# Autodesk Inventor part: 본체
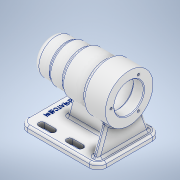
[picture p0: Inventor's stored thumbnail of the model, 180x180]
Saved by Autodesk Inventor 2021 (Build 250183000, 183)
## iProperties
Created: 2022-07
Part Number: 본체
Material: 알루미늄 6061
Document SubType Name: Modeling
Designer: owner
Density: 2.7 g/cm^3
Appearance: 알루미늄 - 평지
Mass: 693.151 g
Surface Area: 698.728 cm^2
Volume: 256.723 cm^3
Author: owner
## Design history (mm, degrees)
sketch "스케치1"
  geometry: L1 (44, 45)-(-44, 45); L2 (-56, 33)-(-56, -33); L3 (-44, -45)-(44, -45); L4 (56, -33)-(56, 33); L5 (56, 45)-(-56, -45); L6 (-56, 45)-(56, -45); L7 (-4, 33)-(-19, 33); L8 (-4, 37.5)-(-19, 37.5); L9 (-19, 28.5)-(-4, 28.5); L10 (36, 33)-(21, 33); L11 (36, 37.5)-(21, 37.5); L12 (21, 28.5)-(36, 28.5); L13 (0, 0)-(-56, 0); L14 (-19, -28.5)-(-4, -28.5); L15 (-4, -37.5)-(-19, -37.5); L16 (21, -28.5)-(36, -28.5); L17 (36, -37.5)-(21, -37.5); A1 r 12 centre (44, -33) between (44, -45) and (56, -33); A2 r 12 centre (-44, -33) between (-56, -33) and (-44, -45); A3 r 12 centre (44, 33) between (56, 33) and (44, 45); A4 r 12 centre (-44, 33) between (-44, 45) and (-56, 33); A5 r 4.5 centre (-4, 33) between (-4, 28.5) and (-4, 37.5); A6 r 4.5 centre (-19, 33) between (-19, 37.5) and (-19, 28.5); A7 r 4.5 centre (36, 33) between (36, 28.5) and (36, 37.5); A8 r 4.5 centre (21, 33) between (21, 37.5) and (21, 28.5); A9 r 4.5 centre (-4, -33) between (-4, -37.5) and (-4, -28.5); A10 r 4.5 centre (-19, -33) between (-19, -28.5) and (-19, -37.5); A11 r 4.5 centre (36, -33) between (36, -37.5) and (36, -28.5); A12 r 4.5 centre (21, -33) between (21, -28.5) and (21, -37.5); 2 further points
  constraints: 38 end point, 24 point on circle, 16 tangent, 12 centre point, 12 symmetric about line, 8 point on line, 5 midpoint, 4 parallel, 3 equal radius, 3 horizontal, 1 collinear, 1 perpendicular, 4 other
  dimensions: "d0" = 112 distance of L5.end L6.end; "d1" = 90 distance of L6.end L5.start; "d2" = 12 radius of A1; "d4" = 15 distance of L10.start L10.end; "d5" = 9 distance between parallel lines of L11 L12; "d6" = 20 distance from line of L4 L10.start; "d7" = 33 distance from line of L13 point (28.5, 33); "d8" = 9 distance between parallel lines of L8 L9; "d9" = 15 distance of L7.start L7.end; "d10" = 25 distance of L10.end L7.start
extrude "돌출1" new body sketch "스케치1" distance "d11" = 8; taper "d12" = 0 deg
sketch "스케치2"
  geometry: L1 (-56, 70)-(56, 70); L2 (-44, 0)-(44, 0) reference; L3 (56, 0)-(44, 0) reference; L4 (56, 0)-(56, 70); L5 (56, 70)-(56, 104); L6 (56, 104)-(24, 104); L7 (24, 104)-(24, 100); L8 (24, 100)-(-10, 100); L9 (-10, 100)-(-10, 97); L10 (-10, 97)-(-32, 97); L11 (-32, 97)-(-32, 95); L12 (-32, 95)-(-48, 95); L13 (-56, 87)-(-56, 70); L14 (56, 91)-(41, 91); L15 (41, 91)-(41, 91); L16 (38, 94)-(-10, 94); L17 (-13, 91)-(-13, 91); L18 (-13, 91)-(-24.7, 91); L19 (-25, 90.7)-(-25, 87.5); L20 (-25, 87.5)-(-42.7, 87.5); L21 (-43, 87.2)-(-43, 86); L22 (-43, 86)-(-46.7, 86); L23 (-47, 85.7)-(-47, 80.5); L24 (-47, 80.5)-(-47, 80.5); L25 (-50, 77.5)-(-50, 70); A1 r 0.3 centre (-46.7, 85.7) between (-46.7, 86) and (-47, 85.7); A2 r 0.3 centre (-42.7, 87.2) between (-42.7, 87.5) and (-43, 87.2); A3 r 0.3 centre (-24.7, 90.7) between (-24.7, 91) and (-25, 90.7); A4 r 3 centre (-47, 77.5) between (-47, 80.5) and (-50, 77.5); A5 r 3 centre (-10, 91) between (-10, 94) and (-13, 91); A6 r 3 centre (38, 91) between (41, 91) and (38, 94); A7 r 8 centre (-48, 87) between (-48, 95) and (-56, 87); 10 further points
  constraints: 46 end point, 16 perpendicular, 16 point on line, 14 point on circle, 14 tangent, 7 centre point, 4 equal radius, 4 vertical, 2 horizontal
  dimensions: "d14" = 70 distance of L3.start L1.end; "d15" = 112 distance of L1.start L1.end; "d16" = 68 diameter of L6 L1; "d17" = 60 diameter of L8 L1; "d18" = 54 diameter of L10 L1; "d19" = 50 diameter of L12 L1; "d20" = 80 distance between parallel lines of L7 L13; "d21" = 46 distance between parallel lines of L9 L13; "d22" = 24 distance between parallel lines of L11 L13; "d23" = 42 diameter of L14 L1; "d24" = 48 diameter of L16 L1; "d25" = 15 distance of L14.start L14.end; "d26" = 54 distance of point (41, 94) point (-13, 94); "d27" = 12 distance of L17.end point (-25, 91); "d28" = 18 distance of L19.end point (-43, 87.5); "d29" = 35 diameter of L20 L1; "d30" = 32 diameter of L22 L1; "d31" = 21 diameter of L24 L1; "d32" = 4 distance of L21.end point (-47, 86); "d33" = 3 distance of L23.end point (-50, 80.5); "d34" = 0.3 radius of A1; "d35" = 3 radius of A4; "d36" = 8 radius of A7
revolve "회전1" sketch "스케치2" stored, may be unused: angle "d37" = 90 deg
node "작업 평면1"
sketch "스케치4"
  geometry: L1 (-12, 8)-(0, 8) reference; L2 (0, 8)-(66, 8) reference; L3 (66, 8)-(78, 8) reference; L4 (78, 8)-(66, 8) reference; L5 (66, 8)-(0, 8) reference; L6 (0, 8)-(-12, 8) reference; L7 (61.5, 8)-(70.5, 8) reference; L8 (70.5, 8)-(61.5, 8) reference; L9 (70.5, 8)-(61.5, 8) reference; L10 (61.5, 8)-(70.5, 8) reference; L11 (-4.5, 8)-(4.5, 8) reference; L12 (4.5, 8)-(-4.5, 8) reference; L13 (-4.5, 8)-(4.5, 8) reference; L14 (4.5, 8)-(-4.5, 8) reference; L15 (9.591, 45.342)-(-4, 8); L16 (56.409, 45.342)-(70, 8); A1 r 34 centre (33, 70) between (56.409, 45.342) and (9.591, 45.342) reference; 3 further points
  constraints: 4 end point, 2 point on circle, 2 point on line
  dimensions: "d40" = 110 deg angle of L6 L15; "d41" = 110 deg angle of L3 L16; "d42" = 8 distance of L1.start L15.end; "d43" = 8 distance of L3.end L16.end
extrude "돌출2" join sketch "스케치4" distance "d44" = 8; taper "d45" = 0 deg
sketch "스케치5"
  geometry: L1 (40, 8)-(48, 8) reference; L2 (48, 8)-(40, 8) reference; L3 (44, 8)-(56, 8) reference; L4 (56, 8)-(44, 8) reference; L5 (44, 8)-(-44, 8) reference; L6 (-44, 8)-(-56, 8) reference; L7 (-56, 8)-(-44, 8) reference; L8 (-44, 8)-(44, 8) reference; L9 (-21, 8)-(-36, 8) reference; L10 (-36, 8)-(-36, 8) reference; L11 (-36, 8)-(-21, 8) reference; L12 (-21, 8)-(-21, 8) reference; L13 (4, 8)-(19, 8) reference; L14 (19, 8)-(19, 8) reference; L15 (19, 8)-(4, 8) reference; L16 (4, 8)-(4, 8) reference; L17 (-36, 8)-(-36, 8) reference; L18 (-36, 8)-(-21, 8) reference; L19 (-21, 8)-(-21, 8) reference; L20 (-21, 8)-(-36, 8) reference; L21 (4, 8)-(4, 8) reference; L22 (4, 8)-(19, 8) reference; L23 (19, 8)-(19, 8) reference; L24 (19, 8)-(4, 8) reference; L25 (-29, 8)-(-19.622, 43); L26 (-32, 43)-(-10, 43) reference; 1 further point
  constraints: 2 end point, 2 point on line
  dimensions: "d46" = 105 deg angle of L8 L25; "d47" = 77 distance of L25.start L1.end
feature "리브1" sketch "스케치5" dims "d48" = 1, "d49" = 8, "d50" = 0, "d51" = 0, "d52" = 1, "d53" = 1
sketch "스케치6"
  geometry: L1 (0, 0)-(13, 22.517); L2 (0, 0)-(-26, 0); C1 r 7.5 at (0, 0) reference; A1 r 26 centre (0, 0) between (13, 22.517) and (-26, 0); 2 further points
  constraints: 4 end point, 3 point on circle, 1 centre point, 1 coincident, 1 horizontal, 1 point on line
  dimensions: "d54" = 52 diameter of A1; "d55" = 120 deg angle of L1 L2
hole "구멍1" sketch "스케치6" at (13, 22.517) diameter "d56" = 3.242; stored, may be unused: countersink angle "d60" = 90 deg, drill point angle "d62" = 118 deg; dims "d57" = 8, "d58" = 4, "d59" = 2, "d61" = 11
fillet "모깎기1" dims "d66" = 3
chamfer "모따기1" distance "d67" = 1; stored, may be unused: second distance "d68" = 2, angle "d69" = 45 deg
fillet "모깎기2" dims "d70" = 3
fillet "모깎기3" dims "d71" = 3
sketch "스케치7"
  geometry: L1 (0, 0)-(-44, 0); L2 (-56, 33)-(-56, -33) reference; 1 further point
  constraints: 2 end point, 1 coincident, 1 horizontal, 1 other
  dimensions: "d72" = 12 distance from line of L2 point (-44, 0)
feature "엠보싱1" sketch "스케치7" dims "d0" = 112, "d1" = 90, "d2" = 12, "d4" = 15, "d5" = 9, "d6" = 20, "d7" = 33, "d8" = 9, "d9" = 15, "d10" = 25, "d73" = 0.5, "d74" = 0
node "솔리드1"
pattern_circular "원형 패턴1" dims angle "d64" = 360 deg
node "투영된 루프1"
node "투영된 루프2"
other parameters: "d39" = -8
